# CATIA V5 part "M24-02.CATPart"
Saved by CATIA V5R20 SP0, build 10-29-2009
Part number: M24-02
Revision: ANY
Definition: UNKNOWN
Nomenclature: M24-02
Source: Unknown
Bounding box of the stored display mesh (mm): x -15 to 15, y -15 to 15, z 0 to 170
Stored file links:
  C:\Users\Utente\Desktop\IO LAVORO\3D X SITO CF\X 3D SITO CF 27-09-2020\740T\740T-24\M24-02.CATPart
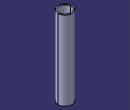
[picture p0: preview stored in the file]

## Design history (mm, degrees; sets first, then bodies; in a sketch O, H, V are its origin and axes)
Body1 "NONE" (main body)
  Solid1: solid without history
